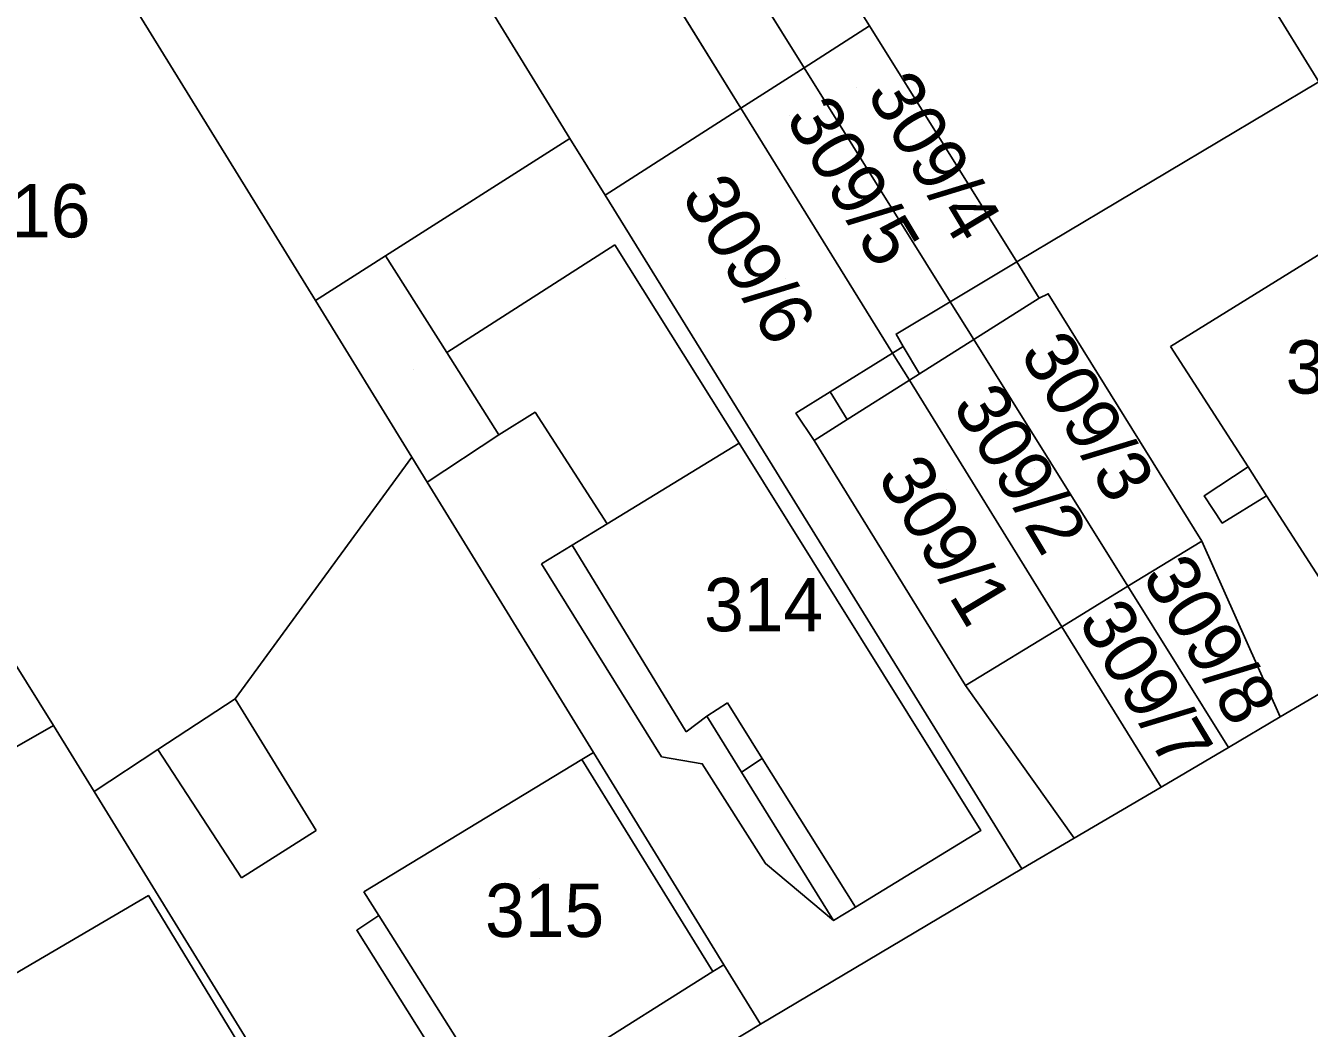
# Model space of a CAD drawing. Extents: x -263943 to -261149, y -1236934 to -1230686.
# Drawn here: x -262592.15 to -262544.07, y -1235744.96 to -1235707.41 of the extents above; entities that cross this region are included whole.
import ezdxf

# ---------------------------------------------------------------- set-up
doc = ezdxf.new("R2010")
doc.units = 0
for name, color, linetype in [('body_kn', 7, 'Continuous'), ('kladpar_druhypozemkov', 7, 'Continuous'), ('kladpar_hranice', 7, 'Continuous'), ('kladpar_parcelnecisla', 7, 'Continuous'), ('kladpar_plochy', 7, 'Continuous'), ('zappar_hrandruhpozemk', 7, 'Continuous')]:
    doc.layers.add(name, color=color, linetype=linetype)

msp = doc.modelspace()

# ---------------------------------------------------------------- linework, layer by layer
at = {"layer": 'body_kn'}
for p, q in [((-262560.54, -1235707.42), (-262560.54, -1235707.42)), ((-262560.54, -1235707.42), (-262560.54, -1235707.42)), ((-262562.99, -1235708.99), (-262562.99, -1235708.99)), ((-262562.99, -1235708.99), (-262562.99, -1235708.99)), ((-262565.36, -1235710.5), (-262565.36, -1235710.5)), ((-262565.36, -1235710.5), (-262565.36, -1235710.5)), ((-262571.77, -1235711.63), (-262571.77, -1235711.63)), ((-262570.45, -1235713.76), (-262570.45, -1235713.76)), ((-262570.08, -1235715.62), (-262570.08, -1235715.62)), ((-262578.68, -1235716.03), (-262578.68, -1235716.03)), ((-262578.68, -1235716.03), (-262578.68, -1235716.03)), ((-262555.03, -1235716.26), (-262555.03, -1235716.26)), ((-262555.03, -1235716.26), (-262555.03, -1235716.26)), ((-262554.19, -1235717.62), (-262554.19, -1235717.62)), ((-262554.19, -1235717.62), (-262554.19, -1235717.62)), ((-262553.85, -1235717.45), (-262553.85, -1235717.45)), ((-262581.3, -1235717.7), (-262581.3, -1235717.7)), ((-262581.3, -1235717.7), (-262581.3, -1235717.7)), ((-262557.52, -1235717.75), (-262557.52, -1235717.75)), ((-262559.55, -1235718.96), (-262559.55, -1235718.96)), ((-262559.28, -1235719.42), (-262559.28, -1235719.42)), ((-262556.64, -1235719.16), (-262556.64, -1235719.16)), ((-262556.64, -1235719.16), (-262556.64, -1235719.16)), ((-262549.27, -1235719.42), (-262549.27, -1235719.42)), ((-262576.38, -1235719.65), (-262576.38, -1235719.65)), ((-262559.69, -1235719.67), (-262559.69, -1235719.67)), ((-262559.69, -1235719.67), (-262559.69, -1235719.67)), ((-262558.67, -1235720.45), (-262558.67, -1235720.45)), ((-262558.67, -1235720.45), (-262558.67, -1235720.45)), ((-262559.05, -1235720.69), (-262559.05, -1235720.69)), ((-262559.05, -1235720.69), (-262559.05, -1235720.69)), ((-262562.02, -1235721.12), (-262562.02, -1235721.12)), ((-262562.02, -1235721.12), (-262562.02, -1235721.12)), ((-262573.07, -1235721.89), (-262573.07, -1235721.89)), ((-262563.3, -1235721.92), (-262563.3, -1235721.92)), ((-262561.38, -1235722.16), (-262561.38, -1235722.16)), ((-262574.43, -1235722.73), (-262574.43, -1235722.73)), ((-262574.43, -1235722.73), (-262574.43, -1235722.73)), ((-262562.62, -1235722.94), (-262562.62, -1235722.94)), ((-262562.62, -1235722.94), (-262562.62, -1235722.94)), ((-262565.43, -1235723.05), (-262565.43, -1235723.05)), ((-262577.69, -1235723.57), (-262577.69, -1235723.57)), ((-262546.36, -1235723.93), (-262546.36, -1235723.93)), ((-262577.11, -1235724.51), (-262577.11, -1235724.51)), ((-262548.01, -1235725.02), (-262548.01, -1235725.02)), ((-262545.67, -1235725.02), (-262545.67, -1235725.02)), ((-262545.67, -1235725.02), (-262545.67, -1235725.02)), ((-262570.37, -1235726.07), (-262570.37, -1235726.07)), ((-262547.33, -1235726.04), (-262547.33, -1235726.04)), ((-262548.1, -1235726.71), (-262548.1, -1235726.71)), ((-262548.1, -1235726.71), (-262548.1, -1235726.71)), ((-262571.68, -1235726.87), (-262571.68, -1235726.87)), ((-262572.83, -1235727.57), (-262572.83, -1235727.57)), ((-262550.87, -1235728.4), (-262550.87, -1235728.4)), ((-262553.34, -1235729.92), (-262553.34, -1235729.92)), ((-262553.34, -1235729.92), (-262553.34, -1235729.92)), ((-262556.95, -1235732.12), (-262556.95, -1235732.12)), ((-262556.95, -1235732.12), (-262556.95, -1235732.12)), ((-262584.31, -1235732.62), (-262584.31, -1235732.62)), ((-262584.31, -1235732.62), (-262584.31, -1235732.62)), ((-262565.87, -1235732.77), (-262565.87, -1235732.77)), ((-262565.87, -1235732.77), (-262565.87, -1235732.77)), ((-262566.64, -1235733.27), (-262566.64, -1235733.27)), ((-262566.64, -1235733.27), (-262566.64, -1235733.27)), ((-262545.16, -1235733.3), (-262545.16, -1235733.3)), ((-262591.11, -1235733.62), (-262591.11, -1235733.62)), ((-262567.41, -1235733.86), (-262567.41, -1235733.86)), ((-262547.1, -1235734.44), (-262547.1, -1235734.44)), ((-262547.1, -1235734.44), (-262547.1, -1235734.44)), ((-262587.21, -1235734.52), (-262587.21, -1235734.52)), ((-262571.32, -1235734.89), (-262571.32, -1235734.89)), ((-262570.89, -1235734.63), (-262570.89, -1235734.63)), ((-262570.89, -1235734.63), (-262570.89, -1235734.63)), ((-262568.34, -1235734.79), (-262568.34, -1235734.79)), ((-262564.57, -1235734.85), (-262564.57, -1235734.85)), ((-262566.81, -1235735.05), (-262566.81, -1235735.05)), ((-262565.34, -1235735.37), (-262565.34, -1235735.37)), ((-262565.34, -1235735.37), (-262565.34, -1235735.37)), ((-262549.62, -1235735.93), (-262549.62, -1235735.93)), ((-262549.62, -1235735.93), (-262549.62, -1235735.93)), ((-262589.59, -1235736.09), (-262589.59, -1235736.09)), ((-262581.27, -1235737.55), (-262581.27, -1235737.55)), ((-262556.37, -1235737.55), (-262556.37, -1235737.55)), ((-262552.88, -1235737.84), (-262552.88, -1235737.84)), ((-262564.44, -1235738.79), (-262564.44, -1235738.79)), ((-262554.84, -1235738.99), (-262554.84, -1235738.99)), ((-262554.84, -1235738.99), (-262554.84, -1235738.99)), ((-262584.07, -1235739.33), (-262584.07, -1235739.33)), ((-262587.56, -1235739.99), (-262587.56, -1235739.99)), ((-262579.49, -1235739.85), (-262579.49, -1235739.85)), ((-262578.92, -1235740.74), (-262578.92, -1235740.74)), ((-262561.07, -1235740.42), (-262561.07, -1235740.42)), ((-262561.9, -1235740.92), (-262561.9, -1235740.92)), ((-262561.9, -1235740.92), (-262561.9, -1235740.92)), ((-262579.75, -1235741.29), (-262579.75, -1235741.29)), ((-262566, -1235742.58), (-262566, -1235742.58)), ((-262566, -1235742.58), (-262566, -1235742.58)), ((-262566.41, -1235742.83), (-262566.41, -1235742.83)), ((-262566.41, -1235742.83), (-262566.41, -1235742.83)), ((-262564.63, -1235744.81), (-262564.63, -1235744.81)), ((-262564.63, -1235744.81), (-262564.63, -1235744.81))]:
    msp.add_line(p, q, dxfattribs=at)
at = {"layer": 'kladpar_druhypozemkov'}
for p, q in [((-262561.03, -1235709.72), (-262561.03, -1235709.72)), ((-262563.56, -1235710.76), (-262563.56, -1235710.76)), ((-262563.69, -1235716.86), (-262563.69, -1235716.86)), ((-262577.63, -1235720.28), (-262577.63, -1235720.28)), ((-262551.29, -1235722.45), (-262551.29, -1235722.45)), ((-262554.35, -1235724), (-262554.35, -1235724)), ((-262557.68, -1235724.77), (-262557.68, -1235724.77)), ((-262564.9, -1235728.44), (-262564.9, -1235728.44)), ((-262548.27, -1235728.94), (-262548.27, -1235728.94)), ((-262551.34, -1235730.18), (-262551.34, -1235730.18)), ((-262572.9, -1235739.34), (-262572.9, -1235739.34))]:
    msp.add_line(p, q, dxfattribs=at)
at = {"layer": 'kladpar_hranice'}
for p, q in [((-262565.36, -1235710.5), (-262631.97, -1235602.9)), ((-262631.97, -1235602.9), (-262565.36, -1235710.5)), ((-262562.99, -1235708.99), (-262591.76, -1235662.87)), ((-262591.76, -1235662.87), (-262562.99, -1235708.99)), ((-262562.99, -1235708.99), (-262560.54, -1235707.42)), ((-262562.99, -1235708.99), (-262565.36, -1235710.5)), ((-262565.36, -1235710.5), (-262562.99, -1235708.99)), ((-262562.99, -1235708.99), (-262557.52, -1235717.75)), ((-262557.52, -1235717.75), (-262562.99, -1235708.99)), ((-262565.36, -1235710.5), (-262559.69, -1235719.67)), ((-262559.69, -1235719.67), (-262565.36, -1235710.5)), ((-262557.52, -1235717.75), (-262555.03, -1235716.26)), ((-262550.87, -1235728.4), (-262548.1, -1235726.71)), ((-262553.34, -1235729.92), (-262550.87, -1235728.4)), ((-262550.87, -1235728.4), (-262553.34, -1235729.92)), ((-262547.1, -1235734.44), (-262550.87, -1235728.4)), ((-262550.87, -1235728.4), (-262547.1, -1235734.44)), ((-262549.62, -1235735.93), (-262553.34, -1235729.92)), ((-262553.34, -1235729.92), (-262549.62, -1235735.93)), ((-262547.1, -1235734.44), (-262549.62, -1235735.93))]:
    msp.add_line(p, q, dxfattribs=at)
for points in [[(-262565.36, -1235710.5), (-262570.45, -1235713.76), (-262571.77, -1235711.63), (-262582.68, -1235693.86), (-262604.66, -1235658.08), (-262612.77, -1235644.65), (-262624.69, -1235625.35), (-262636.17, -1235606.78), (-262637.36, -1235604.86), (-262631.97, -1235602.9)], [(-262581.3, -1235717.7), (-262592.89, -1235698.92), (-262599.54, -1235688.02), (-262606, -1235677.44), (-262609.54, -1235671.64), (-262612.61, -1235666.71), (-262619.18, -1235656.17), (-262622.65, -1235650.47), (-262612.77, -1235644.65), (-262604.66, -1235658.08), (-262582.68, -1235693.86), (-262571.77, -1235711.63), (-262578.68, -1235716.03), (-262581.3, -1235717.7)], [(-262589.21, -1235661.27), (-262571.62, -1235689.74), (-262560.54, -1235707.42), (-262562.99, -1235708.99)], [(-262555.03, -1235716.26), (-262560.54, -1235707.42), (-262571.62, -1235689.74), (-262565.92, -1235686.28), (-262560.13, -1235682.74), (-262545.7, -1235706.28), (-262543.72, -1235709.51), (-262555.03, -1235716.26)], [(-262606.17, -1235742.23), (-262610.32, -1235735.09), (-262635.09, -1235692.85), (-262621.32, -1235684.76), (-262607.02, -1235708.12), (-262591.11, -1235733.62), (-262606.17, -1235742.23)], [(-262584.31, -1235732.62), (-262587.21, -1235734.52), (-262589.59, -1235736.09), (-262591.11, -1235733.62), (-262607.02, -1235708.12), (-262605.76, -1235707.3), (-262592.89, -1235698.92), (-262581.3, -1235717.7), (-262577.69, -1235723.57), (-262584.31, -1235732.62)], [(-262543.72, -1235709.51), (-262545.7, -1235706.28), (-262542.51, -1235704.17), (-262540.48, -1235707.4), (-262538.96, -1235709.69), (-262542.27, -1235711.91), (-262543.72, -1235709.51)], [(-262560.54, -1235707.42), (-262555.03, -1235716.26), (-262557.52, -1235717.75)], [(-262541.42, -1235731.1), (-262545.16, -1235733.3), (-262548.1, -1235726.71), (-262553.85, -1235717.45), (-262554.19, -1235717.62), (-262555.03, -1235716.26), (-262543.72, -1235709.51), (-262542.27, -1235711.91), (-262533.48, -1235726.42), (-262541.42, -1235731.1)], [(-262554.84, -1235738.99), (-262570.45, -1235713.76), (-262565.36, -1235710.5)], [(-262564.63, -1235744.81), (-262566, -1235742.58), (-262570.89, -1235734.63), (-262577.11, -1235724.51), (-262577.69, -1235723.57), (-262581.3, -1235717.7), (-262578.68, -1235716.03), (-262571.77, -1235711.63), (-262570.45, -1235713.76), (-262554.84, -1235738.99), (-262564.63, -1235744.81)], [(-262555.03, -1235716.26), (-262554.19, -1235717.62), (-262553.85, -1235717.45), (-262548.1, -1235726.71), (-262550.87, -1235728.4)], [(-262557.52, -1235717.75), (-262559.55, -1235718.96), (-262559.28, -1235719.42), (-262559.69, -1235719.67)], [(-262559.69, -1235719.67), (-262559.28, -1235719.42), (-262559.55, -1235718.96), (-262557.52, -1235717.75)], [(-262550.87, -1235728.4), (-262556.64, -1235719.16), (-262557.52, -1235717.75)], [(-262557.52, -1235717.75), (-262556.64, -1235719.16), (-262550.87, -1235728.4)], [(-262559.69, -1235719.67), (-262562.02, -1235721.12), (-262563.3, -1235721.92), (-262562.62, -1235722.94), (-262556.95, -1235732.12), (-262553.34, -1235729.92)], [(-262553.34, -1235729.92), (-262556.95, -1235732.12), (-262562.62, -1235722.94), (-262563.3, -1235721.92), (-262562.02, -1235721.12), (-262559.69, -1235719.67)], [(-262553.34, -1235729.92), (-262559.05, -1235720.69), (-262559.69, -1235719.67)], [(-262559.69, -1235719.67), (-262559.05, -1235720.69), (-262553.34, -1235729.92)], [(-262573.11, -1235749.92), (-262573.99, -1235750.45), (-262578.93, -1235753.42), (-262589.59, -1235736.09), (-262587.21, -1235734.52), (-262584.31, -1235732.62), (-262577.69, -1235723.57), (-262577.11, -1235724.51), (-262570.89, -1235734.63), (-262566, -1235742.58), (-262564.63, -1235744.81), (-262573.11, -1235749.92)], [(-262548.1, -1235726.71), (-262545.16, -1235733.3), (-262547.1, -1235734.44)], [(-262564.63, -1235744.81), (-262554.84, -1235738.99), (-262552.88, -1235737.84), (-262549.62, -1235735.93), (-262547.1, -1235734.44), (-262545.16, -1235733.3), (-262541.42, -1235731.1)], [(-262595.45, -1235760.39), (-262600.98, -1235751.03), (-262606.17, -1235742.23), (-262591.11, -1235733.62), (-262589.59, -1235736.09), (-262578.93, -1235753.42), (-262594.24, -1235762.45), (-262595.45, -1235760.39)], [(-262549.62, -1235735.93), (-262552.88, -1235737.84), (-262554.84, -1235738.99)], [(-262618.91, -1235776.72), (-262615.07, -1235774.48), (-262611.32, -1235772.3), (-262610.56, -1235771.86), (-262605.13, -1235768.7), (-262594.24, -1235762.45), (-262578.93, -1235753.42), (-262573.99, -1235750.45), (-262573.11, -1235749.92), (-262564.63, -1235744.81)]]:
    msp.add_lwpolyline(points, dxfattribs=at)
at = {"layer": 'kladpar_plochy'}
for points in [[(-262562.99, -1235708.99), (-262565.36, -1235710.5), (-262631.97, -1235602.9), (-262629.39, -1235601.96), (-262598.02, -1235652.59), (-262591.76, -1235662.87)], [(-262565.36, -1235710.5), (-262570.45, -1235713.76), (-262571.77, -1235711.63), (-262582.68, -1235693.86), (-262604.66, -1235658.08), (-262612.77, -1235644.65), (-262624.69, -1235625.35), (-262636.17, -1235606.78), (-262637.36, -1235604.86), (-262631.97, -1235602.9)], [(-262581.3, -1235717.7), (-262592.89, -1235698.92), (-262599.54, -1235688.02), (-262606, -1235677.44), (-262609.54, -1235671.64), (-262612.61, -1235666.71), (-262619.18, -1235656.17), (-262622.65, -1235650.47), (-262612.77, -1235644.65), (-262604.66, -1235658.08), (-262582.68, -1235693.86), (-262571.77, -1235711.63), (-262578.68, -1235716.03)], [(-262589.21, -1235661.27), (-262571.62, -1235689.74), (-262560.54, -1235707.42), (-262562.99, -1235708.99), (-262591.76, -1235662.87)], [(-262555.03, -1235716.26), (-262560.54, -1235707.42), (-262571.62, -1235689.74), (-262565.92, -1235686.28), (-262560.13, -1235682.74), (-262545.7, -1235706.28), (-262543.72, -1235709.51)], [(-262606.17, -1235742.23), (-262610.32, -1235735.09), (-262635.09, -1235692.85), (-262621.32, -1235684.76), (-262607.02, -1235708.12), (-262591.11, -1235733.62)], [(-262584.31, -1235732.62), (-262587.21, -1235734.52), (-262589.59, -1235736.09), (-262591.11, -1235733.62), (-262607.02, -1235708.12), (-262605.76, -1235707.3), (-262592.89, -1235698.92), (-262581.3, -1235717.7), (-262577.69, -1235723.57)], [(-262543.72, -1235709.51), (-262545.7, -1235706.28), (-262542.51, -1235704.17), (-262540.48, -1235707.4), (-262538.96, -1235709.69), (-262542.27, -1235711.91)], [(-262560.54, -1235707.42), (-262555.03, -1235716.26), (-262557.52, -1235717.75), (-262562.99, -1235708.99)], [(-262565.36, -1235710.5), (-262562.99, -1235708.99), (-262557.52, -1235717.75), (-262559.55, -1235718.96), (-262559.28, -1235719.42), (-262559.69, -1235719.67)], [(-262541.42, -1235731.1), (-262545.16, -1235733.3), (-262548.1, -1235726.71), (-262553.85, -1235717.45), (-262554.19, -1235717.62), (-262555.03, -1235716.26), (-262543.72, -1235709.51), (-262542.27, -1235711.91), (-262533.48, -1235726.42)], [(-262554.84, -1235738.99), (-262570.45, -1235713.76), (-262565.36, -1235710.5), (-262559.69, -1235719.67), (-262562.02, -1235721.12), (-262563.3, -1235721.92), (-262562.62, -1235722.94), (-262556.95, -1235732.12), (-262553.34, -1235729.92), (-262549.62, -1235735.93), (-262552.88, -1235737.84)], [(-262564.63, -1235744.81), (-262566, -1235742.58), (-262570.89, -1235734.63), (-262577.11, -1235724.51), (-262577.69, -1235723.57), (-262581.3, -1235717.7), (-262578.68, -1235716.03), (-262571.77, -1235711.63), (-262570.45, -1235713.76), (-262554.84, -1235738.99)], [(-262555.03, -1235716.26), (-262554.19, -1235717.62), (-262553.85, -1235717.45), (-262548.1, -1235726.71), (-262550.87, -1235728.4), (-262556.64, -1235719.16), (-262557.52, -1235717.75)], [(-262553.34, -1235729.92), (-262559.05, -1235720.69), (-262559.69, -1235719.67), (-262559.28, -1235719.42), (-262559.55, -1235718.96), (-262557.52, -1235717.75), (-262556.64, -1235719.16), (-262550.87, -1235728.4)], [(-262559.69, -1235719.67), (-262559.05, -1235720.69), (-262553.34, -1235729.92), (-262556.95, -1235732.12), (-262562.62, -1235722.94), (-262563.3, -1235721.92), (-262562.02, -1235721.12)], [(-262573.11, -1235749.92), (-262573.99, -1235750.45), (-262578.93, -1235753.42), (-262589.59, -1235736.09), (-262587.21, -1235734.52), (-262584.31, -1235732.62), (-262577.69, -1235723.57), (-262577.11, -1235724.51), (-262570.89, -1235734.63), (-262566, -1235742.58), (-262564.63, -1235744.81)], [(-262548.1, -1235726.71), (-262545.16, -1235733.3), (-262547.1, -1235734.44), (-262550.87, -1235728.4)], [(-262547.1, -1235734.44), (-262549.62, -1235735.93), (-262553.34, -1235729.92), (-262550.87, -1235728.4)], [(-262595.45, -1235760.39), (-262600.98, -1235751.03), (-262606.17, -1235742.23), (-262591.11, -1235733.62), (-262589.59, -1235736.09), (-262578.93, -1235753.42), (-262594.24, -1235762.45)]]:
    msp.add_lwpolyline(points, close=True, dxfattribs=at)
msp.add_lwpolyline([(-262618.91, -1235776.72), (-262615.07, -1235774.48), (-262611.32, -1235772.3), (-262610.56, -1235771.86), (-262605.13, -1235768.7), (-262594.24, -1235762.45), (-262578.93, -1235753.42), (-262573.99, -1235750.45), (-262573.11, -1235749.92), (-262564.63, -1235744.81), (-262554.84, -1235738.99), (-262552.88, -1235737.84), (-262549.62, -1235735.93), (-262547.1, -1235734.44), (-262545.16, -1235733.3), (-262541.42, -1235731.1)], dxfattribs=at)
at = {"layer": 'zappar_hrandruhpozemk'}
for p, q in [((-262549.27, -1235719.42), (-262541.35, -1235714.52)), ((-262576.38, -1235719.65), (-262570.08, -1235715.62)), ((-262578.68, -1235716.03), (-262576.38, -1235719.65)), ((-262554.19, -1235717.62), (-262556.64, -1235719.16)), ((-262558.67, -1235720.45), (-262559.28, -1235719.42)), ((-262556.64, -1235719.16), (-262558.67, -1235720.45)), ((-262546.36, -1235723.93), (-262549.27, -1235719.42)), ((-262576.38, -1235719.65), (-262574.43, -1235722.73)), ((-262559.05, -1235720.69), (-262558.67, -1235720.45)), ((-262562.02, -1235721.12), (-262561.38, -1235722.16)), ((-262574.43, -1235722.73), (-262577.11, -1235724.51)), ((-262570.37, -1235726.07), (-262565.43, -1235723.05)), ((-262545.67, -1235725.02), (-262546.36, -1235723.93)), ((-262543.09, -1235729.02), (-262545.67, -1235725.02)), ((-262567.41, -1235733.86), (-262571.68, -1235726.87)), ((-262568.34, -1235734.79), (-262572.83, -1235727.57)), ((-262556.95, -1235732.12), (-262552.88, -1235737.84)), ((-262584.31, -1235732.62), (-262581.27, -1235737.55)), ((-262566.64, -1235733.27), (-262565.87, -1235732.77)), ((-262584.07, -1235739.33), (-262587.21, -1235734.52)), ((-262571.32, -1235734.89), (-262579.49, -1235739.85)), ((-262570.89, -1235734.63), (-262571.32, -1235734.89)), ((-262571.32, -1235734.89), (-262566.41, -1235742.83)), ((-262565.34, -1235735.37), (-262564.57, -1235734.85)), ((-262581.27, -1235737.55), (-262584.07, -1235739.33)), ((-262579.49, -1235739.85), (-262578.92, -1235740.74)), ((-262578.92, -1235740.74), (-262574.41, -1235747.87)), ((-262566, -1235742.58), (-262566.41, -1235742.83)), ((-262566.41, -1235742.83), (-262574.41, -1235747.87))]:
    msp.add_line(p, q, dxfattribs=at)
for points in [[(-262570.08, -1235715.62), (-262565.43, -1235723.05), (-262556.37, -1235737.55), (-262561.07, -1235740.42), (-262561.9, -1235740.92), (-262565.34, -1235735.37), (-262566.64, -1235733.27), (-262567.41, -1235733.86)], [(-262562.62, -1235722.94), (-262561.38, -1235722.16), (-262559.05, -1235720.69)], [(-262570.37, -1235726.07), (-262573.07, -1235721.89), (-262574.43, -1235722.73)], [(-262546.36, -1235723.93), (-262548.01, -1235725.02), (-262547.33, -1235726.04), (-262545.67, -1235725.02)], [(-262572.83, -1235727.57), (-262571.68, -1235726.87), (-262570.37, -1235726.07)], [(-262565.87, -1235732.77), (-262564.57, -1235734.85), (-262561.07, -1235740.42)], [(-262561.9, -1235740.92), (-262564.44, -1235738.79), (-262566.81, -1235735.05), (-262568.34, -1235734.79)], [(-262596.66, -1235745.31), (-262587.56, -1235739.99), (-262580.45, -1235751.64)], [(-262578.92, -1235740.74), (-262579.75, -1235741.29), (-262573.99, -1235750.45)]]:
    msp.add_lwpolyline(points, dxfattribs=at)

# ---------------------------------------------------------------- texts
at = {"layer": 'kladpar_parcelnecisla'}
for s, rotation, p in [('296/2', 300, (-262544.602, -1235704.352)), ('309/4', 301, (-262560.686, -1235709.938)), ('309/5', 301, (-262563.725, -1235710.871)), ('309/6', 301, (-262567.626, -1235713.788)), ('309/3', 301, (-262554.939, -1235719.68)), ('309/2', 301, (-262557.471, -1235721.634)), ('309/1', 301, (-262560.285, -1235724.309)), ('309/8', 301, (-262550.369, -1235728.038)), ('309/7', 301, (-262552.762, -1235729.709))]:
    msp.add_text(s, height=2, rotation=rotation, dxfattribs=at).set_placement(p)
for s, p in [('316', (-262594.192, -1235715.34)), ('308', (-262544.957, -1235721.19)), ('314', (-262566.742, -1235730.09)), ('315', (-262574.947, -1235741.54))]:
    msp.add_text(s, height=2, dxfattribs=at).set_placement(p)

doc.saveas('drawing.dxf')
